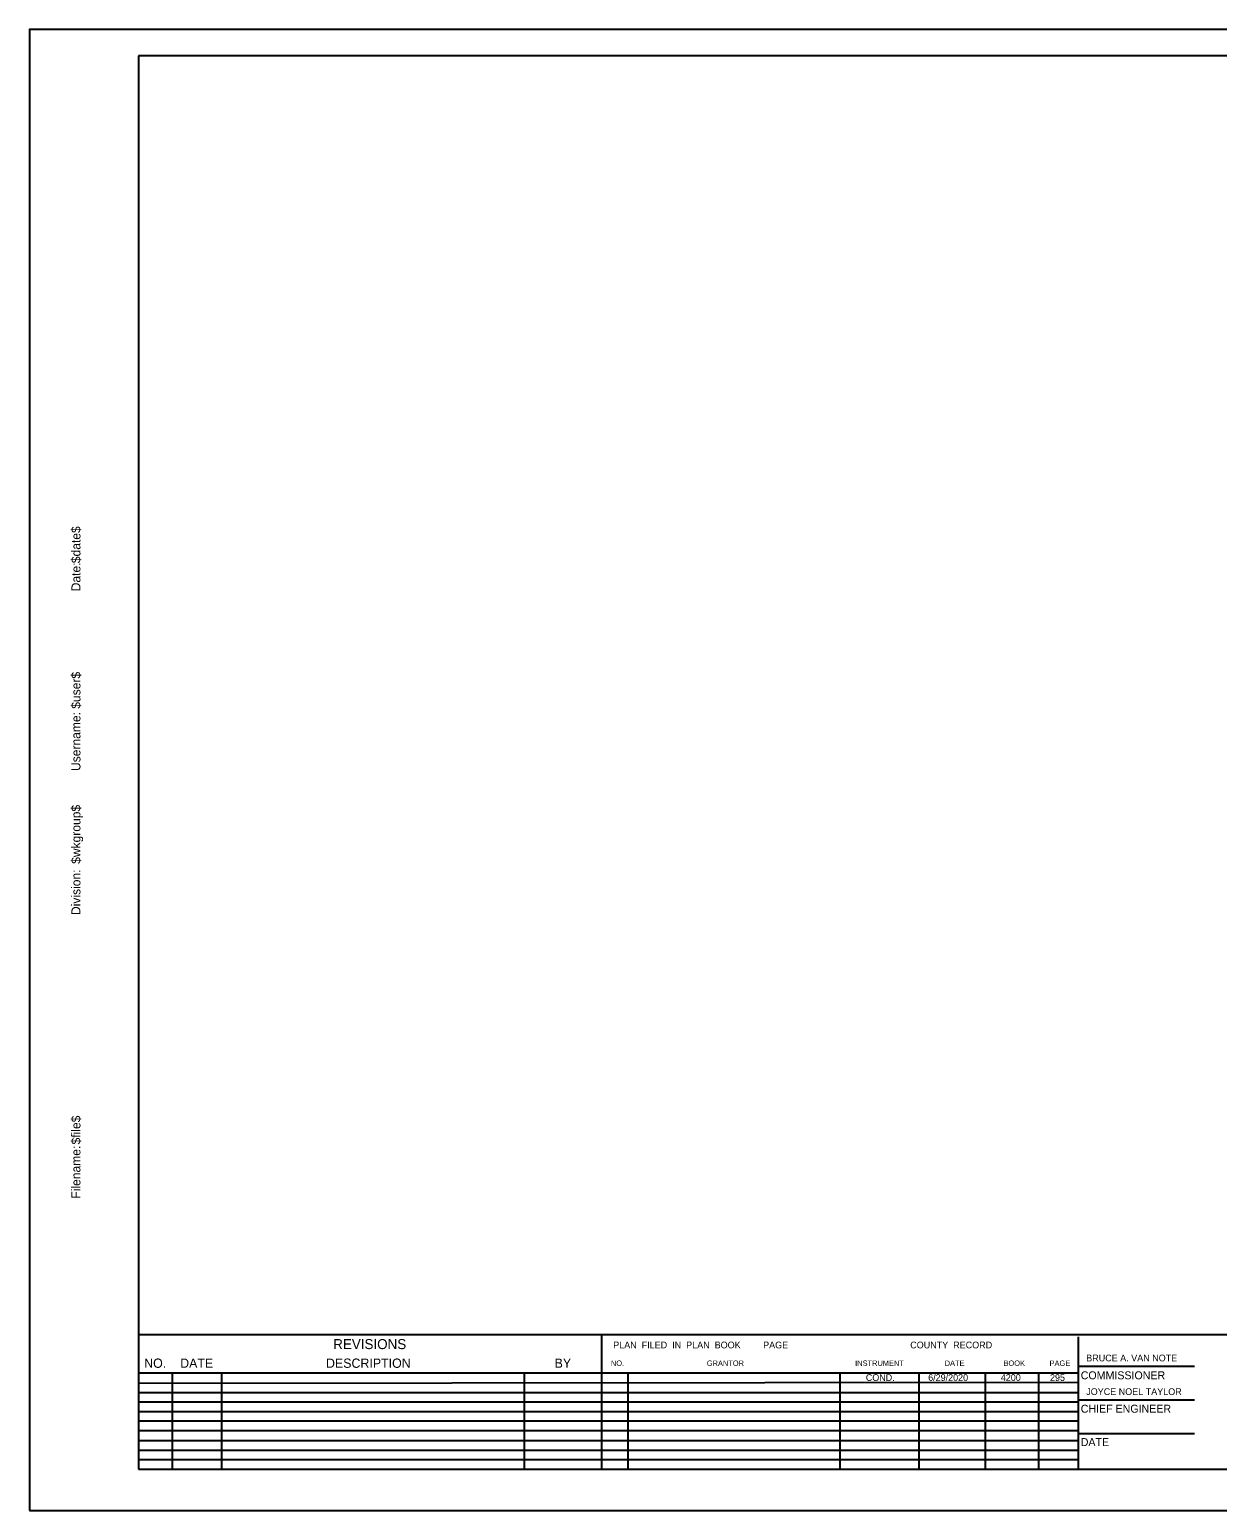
# Model space of a CAD drawing. Extents: x -40 to 810, y -90 to 460.
# Drawn here: x -40 to 401, y -90 to 460 of the extents above; entities that cross this region are included whole.
import ezdxf

# ---------------------------------------------------------------- set-up
doc = ezdxf.new("R2010")
doc.units = 0
for name, color, linetype in [('Border', 7, 'Continuous'), ('EX ROW NOTES', 7, 'Continuous'), ('PLOT BOUNDARY', 7, 'Continuous')]:
    doc.layers.add(name, color=color, linetype=linetype)

msp = doc.modelspace()

# ---------------------------------------------------------------- linework, layer by layer
at = {"layer": 'Border'}
for p, q in [((800, 450), (0, 450)), ((0, 450), (0, -75)), ((0, -24.98), (800, -24.98)), ((172.01, -24.98), (172.01, -75)), ((349.17, -25.78), (349.17, -75)), ((349.17, -36.69), (392.41, -36.69)), ((0, -39.17), (349.17, -39.17)), ((0, -43.1), (349.17, -42.71)), ((12.5, -39.17), (12.5, -75)), ((30.87, -39.17), (30.87, -75)), ((143.37, -39.17), (143.37, -75)), ((181.85, -39.17), (181.85, -75)), ((260.59, -39.17), (260.59, -75)), ((290.12, -75), (290.12, -39.17)), ((314.73, -75), (314.73, -39.17)), ((334.41, -39.17), (334.41, -75)), ((0, -46.45), (349.17, -46.45)), ((349.17, -49.19), (392.41, -49.19)), ((0, -50), (348.98, -50)), ((0, -53.54), (349.17, -53.54)), ((0, -57.08), (349.17, -57.08)), ((0, -60.62), (349.37, -60.62)), ((0, -64.37), (349.17, -64.37)), ((349.17, -61.69), (392.41, -61.69)), ((0, -67.91), (349.17, -67.91)), ((0, -71.45), (349.17, -71.45)), ((0, -75), (800, -75))]:
    msp.add_line(p, q, dxfattribs=at)
at = {"layer": 'PLOT BOUNDARY'}
msp.add_lwpolyline([(-40.47, -90.29), (809.53, -90.29), (809.53, 459.71), (-40.47, 459.71)], close=True, dxfattribs=at)

# ---------------------------------------------------------------- texts
at = {"layer": 'Border'}
for s, height, rotation, p in [('$date$', 3.348, 90, (-21.58, 261.53)), ('Date:', 3.348, 90, (-21.58, 251.09)), ('$user$', 3.348, 90, (-21.58, 207.46)), ('Username:', 3.348, 90, (-21.58, 184.34)), ('$wkgroup$', 3.348, 90, (-21.58, 149.85)), ('Division:', 3.348, 90, (-21.58, 130.84)), ('$file$', 3.348, 90, (-21.58, 45.63)), ('Filename:', 3.348, 90, (-21.58, 25.5)), ('REVISIONS', 3.726, 360, (72.35, -30.39)), ('NO.', 3.445, 360, (2.11, -37.34)), ('DATE', 3.445, 360, (15.48, -37.34)), ('DESCRIPTION', 3.4449, 360, (69.67, -37.34)), ('BY', 3.445, 360, (154.62, -37.34)), ('COMMISSIONER', 2.9528, 360, (350.13, -41.6)), ('CHIEF ENGINEER', 2.9528, 360, (350.13, -54)), ('DATE', 2.953, 360, (350.13, -66.4))]:
    msp.add_text(s, height=height, rotation=rotation, dxfattribs=at).set_placement(p)
for s, height, p in [('PLAN  FILED  IN  PLAN  BOOK         PAGE', 2.4992, (176.4, -30.11)), ('COUNTY  RECORD', 2.4992, (286.77, -30.11)), ('BRUCE A. VAN NOTE', 2.5, (352.17, -34.94)), ('NO.', 2, (175.55, -36.62)), ('GRANTOR', 2, (211.18, -36.62)), ('INSTRUMENT', 2, (266.3, -36.62)), ('DATE', 2, (299.57, -36.62)), ('BOOK', 2, (321.42, -36.62)), ('PAGE', 2, (338.54, -36.62)), ('JOYCE NOEL TAYLOR', 2.5, (352.17, -47.44))]:
    msp.add_text(s, height=height, dxfattribs=at).set_placement(p)
at = {"layer": 'EX ROW NOTES'}
for s, p in [('COND.', (270.27, -42.2)), ('6/29/2020', (293.45, -42.2)), ('4200', (320.44, -42.2)), ('295', (338.71, -42.2))]:
    msp.add_text(s, height=2.49, dxfattribs=at).set_placement(p)

doc.saveas('drawing.dxf')
